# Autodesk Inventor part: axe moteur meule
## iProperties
Shininess: 64.0
Length Units: 11269
Angle Units: 11279
Time Units: 11290
Mass Units: 11283
Length Display Precision: 3
Angle Display Precision: 2
Compacted: True
Part Number: axe moteur meule
Document SubType Name: Modeling
Created: 2005-01
Material: Par défaut
Designer: LEGERET Philippe
Density: 0.0
Volumn: 0.0
Area: 0.0
PropertySet Name: Model Information
Control State: 0
Master: False
Checked Out: False
Author: LEGERET Philippe
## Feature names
1. Extrusion1
2. Chanfrein1 [Chamfer]
3. Extrusion2
4. Perçage1 [Hole]
5. Extrusion3
